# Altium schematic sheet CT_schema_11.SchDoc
size 281 x 153 mm
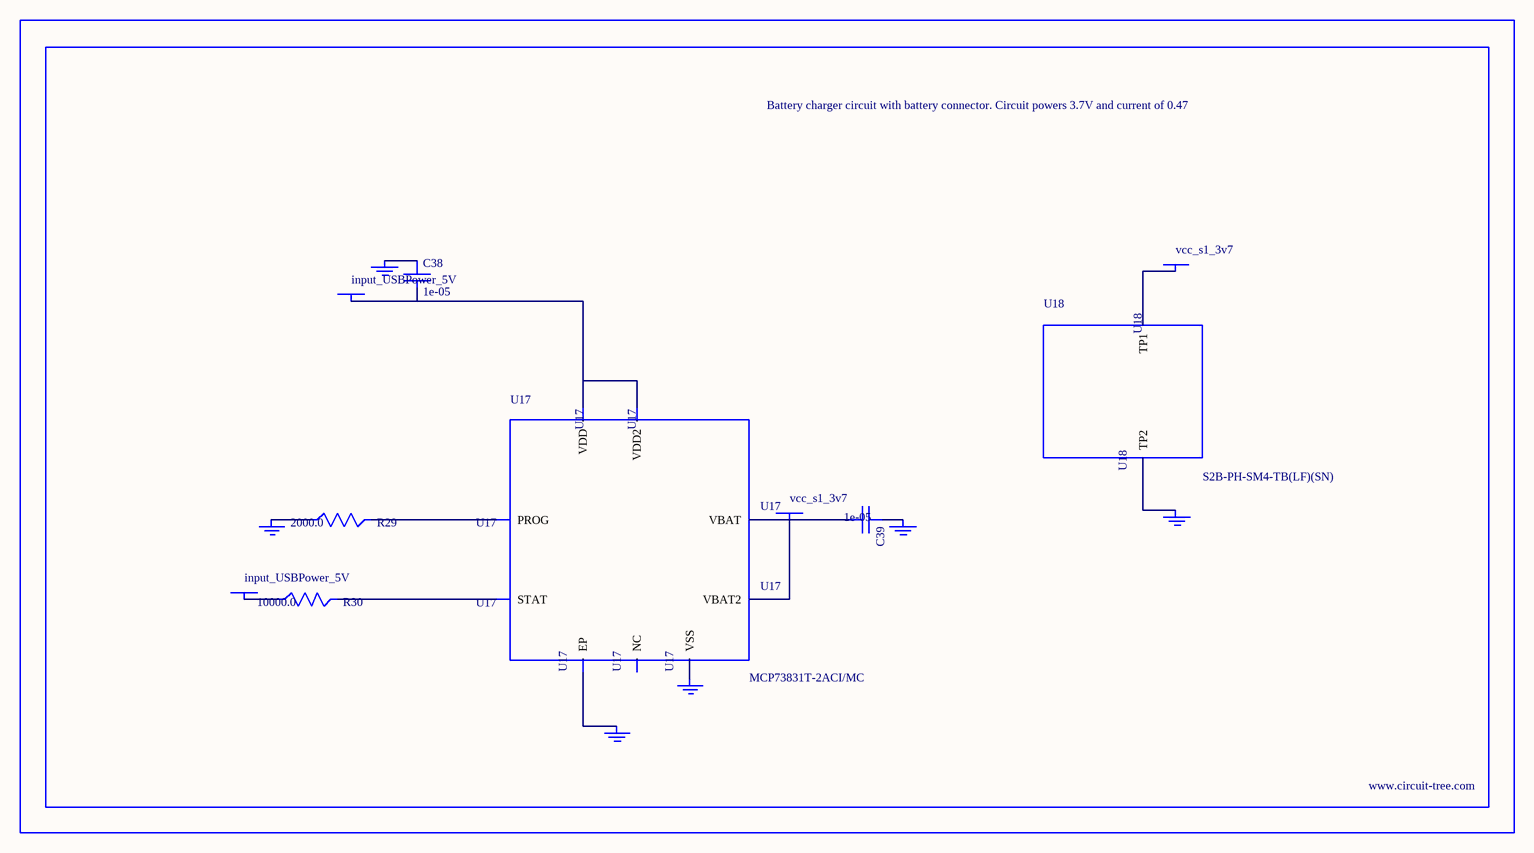
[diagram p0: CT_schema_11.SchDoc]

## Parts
BORDER10  (no value)
C38  1e-05  [C1206]
C39  1e-05  [C1206]
GND_INSTANCE_10_0  (no value)
GND_INSTANCE_10_1  (no value)
GND_INSTANCE_10_2  (no value)
GND_INSTANCE_10_3  (no value)
GND_INSTANCE_10_4  (no value)
GND_INSTANCE_10_5  (no value)
POWER_INSTANCE_10_0  input_USBPower_5V
POWER_INSTANCE_10_1  input_USBPower_5V
POWER_INSTANCE_10_2  vcc_s1_3v7
POWER_INSTANCE_10_3  vcc_s1_3v7
R29  2000.0  [R0603]
R30  10000.0  [R0603]
U17  MCP73831T-2ACI/MC  [DFN8_2X3MC]
U18  S2B-PH-SM4-TB(LF)(SN)  [JST-2-SMD]

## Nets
NetC38_1: C38.1 GND_INSTANCE_10_0.0(GND)
NetC38_2: C38.2 POWER_INSTANCE_10_0.0(PWR) U17.1(VDD) U17.2(VDD2)
NetC39_1: C39.1 GND_INSTANCE_10_1.0(GND)
NetC39_2: C39.2 POWER_INSTANCE_10_2.0(PWR) U17.3(VBAT) U17.4(VBAT2)
NetGND_INSTANCE_10_2_0: GND_INSTANCE_10_2.0(GND) R29.1
NetGND_INSTANCE_10_3_0: GND_INSTANCE_10_3.0(GND) U17.9(EP)
NetGND_INSTANCE_10_4_0: GND_INSTANCE_10_4.0(GND) U17.6(VSS)
NetGND_INSTANCE_10_5_0: GND_INSTANCE_10_5.0(GND) U18.2(TP2)
NetPOWER_INSTANCE_10_1_0: POWER_INSTANCE_10_1.0(PWR) R30.1
NetPOWER_INSTANCE_10_3_0: POWER_INSTANCE_10_3.0(PWR) U18.1(TP1)
NetR29_2: R29.2 U17.8(PROG)
NetR30_2: R30.2 U17.5(STAT)

Not connected (* = marked no-connect by the designer): U17 7(NC)

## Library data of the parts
BORDER10 = BORDER_PAGE10
C38 C39 = C1206C106K3RACTU
GND_INSTANCE_10_0-GND_INSTANCE_10_5 = GND
POWER_INSTANCE_10_0-POWER_INSTANCE_10_3 = PWR
R29 = RC0603JR-072KL
R30 = RC0603JR-0710KL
